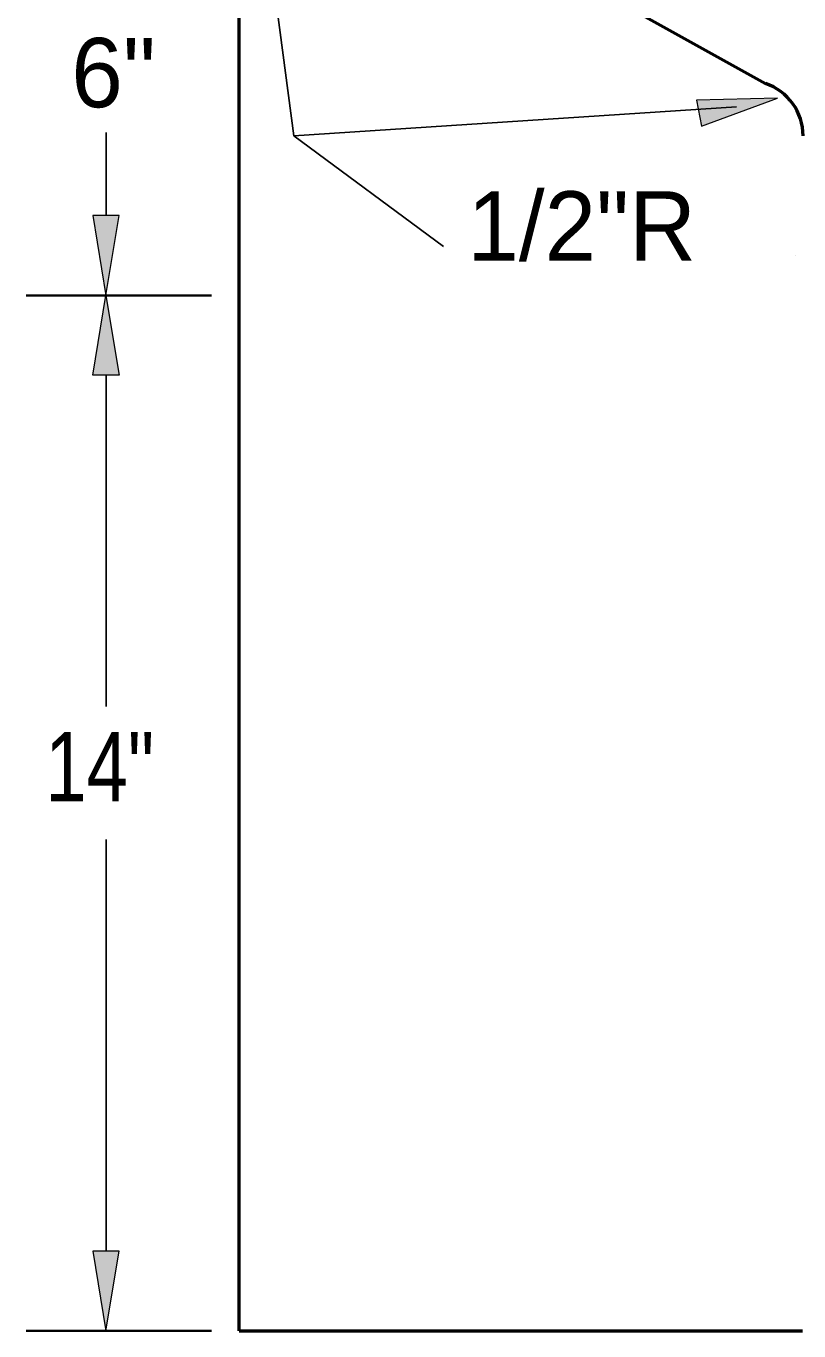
# Model space of a CAD drawing. Extents: x 36.6 to 71.9, y 0.8 to 22.8.
# Drawn here: x 55.429 to 57.17, y 11.515 to 14.457 of the extents above; entities that cross this region are included whole.
import ezdxf

# ---------------------------------------------------------------- set-up
doc = ezdxf.new("R2010")
doc.units = 0
doc.header["$LTSCALE"] = 0.062
for name, color, linetype, lineweight in [('1', 7, 'Continuous', 13), ('3', 7, 'Continuous', 25), ('8', 7, 'Continuous', 13)]:
    doc.layers.add(name, color=color, linetype=linetype, lineweight=lineweight)

msp = doc.modelspace()

# ---------------------------------------------------------------- hatches: boundary and pattern name
at = {"layer": '1'}
for points in [[(55.63867, 14.02983), (55.57867, 14.02983), (55.60858, 13.84983), (55.60858, 13.84983)], [(55.63867, 13.66983), (55.57867, 13.66983), (55.60858, 13.84983), (55.60858, 13.84983)], [(55.63867, 11.69508), (55.57867, 11.69508), (55.60858, 11.51508), (55.60858, 11.51508)]]:
    msp.add_hatch(color=256, dxfattribs=at).paths.add_polyline_path(points)
at = {"layer": '3'}
msp.add_hatch(color=256, dxfattribs=at).paths.add_polyline_path([(56.939, 14.29008), (56.95042, 14.23108), (57.1215, 14.2945), (57.1215, 14.2945)])

# ---------------------------------------------------------------- linework, layer by layer
at = {"layer": '1', "lineweight": 53}
for p, q in [((56.074, 14.89583), (57.09425, 14.3275)), ((55.90883, 11.51508), (55.90883, 14.7775)), ((55.90883, 11.51508), (57.178, 11.51508))]:
    msp.add_line(p, q, dxfattribs=at)
at = {"layer": '1', "lineweight": 25}
for p, q in [((55.60867, 14.02983), (55.60867, 14.21725)), ((55.60867, 12.92275), (55.60867, 13.66983)), ((55.60867, 11.69508), (55.60867, 12.62292))]:
    msp.add_line(p, q, dxfattribs=at)
at = {"layer": '1', "lineweight": 35}
for p, q in [((55.84625, 13.84983), (55.42867, 13.84983)), ((55.84625, 11.51508), (55.42867, 11.51508))]:
    msp.add_line(p, q, dxfattribs=at)
at = {"layer": '1'}
msp.add_line((55.54617, 13.84983), (55.42867, 13.84983), dxfattribs=at)
for points in [[(55.63867, 14.02983), (55.57867, 14.02983), (55.60858, 13.84983), (55.60858, 13.84983)], [(55.63867, 13.66983), (55.57867, 13.66983), (55.60858, 13.84983), (55.60858, 13.84983)], [(55.63867, 11.69508), (55.57867, 11.69508), (55.60858, 11.51508), (55.60858, 11.51508)]]:
    msp.add_lwpolyline(points, close=True, dxfattribs=at)
at = {"layer": '1', "lineweight": 53}
msp.add_arc((57.054, 14.20917), 0.125, 0, 71.23187, dxfattribs=at)
at = {"layer": '3'}
msp.add_line((57.02933, 14.27517), (56.03158, 14.20958), dxfattribs=at)
msp.add_lwpolyline([(55.96908, 14.68775), (56.03158, 14.20958), (56.36908, 13.96008)], dxfattribs=at)
at = {"layer": '3', "lineweight": 13}
msp.add_lwpolyline([(56.939, 14.29008), (56.95042, 14.23108), (57.1215, 14.2945), (57.1215, 14.2945)], close=True, dxfattribs=at)
at = {"layer": '8'}
for p, q in [((57.16108, 13.93933), (57.16117, 13.93933)), ((55.60867, 13.84983), (55.60875, 13.84983)), ((55.60867, 13.84983), (55.60875, 13.84983)), ((55.90875, 13.84983), (55.90883, 13.84983)), ((55.90875, 11.51508), (55.90883, 11.51508))]:
    msp.add_line(p, q, dxfattribs=at)

# ---------------------------------------------------------------- texts
at = {"layer": '1'}
msp.add_text('6"', height=0.1562, dxfattribs=at).set_placement((55.5305, 14.27392))
at = {"layer": '1', "width": 0.8}
msp.add_text('14"', height=0.1562, dxfattribs=at).set_placement((55.472, 12.70892))
at = {"layer": '3'}
msp.add_text('1/2"R', height=0.1562, dxfattribs=at).set_placement((56.4225, 13.92825))

doc.saveas('drawing.dxf')
